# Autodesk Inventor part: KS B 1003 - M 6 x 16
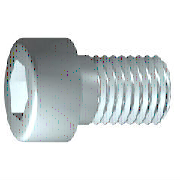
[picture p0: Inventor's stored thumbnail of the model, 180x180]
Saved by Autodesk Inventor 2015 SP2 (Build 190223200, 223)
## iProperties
Created: 2009-02
Part Number: KS B 1003 - M 6 x 16
Material: Steel, Mild
Description: 6각머리 태핑 나사
Document SubType Name: Modeling
Standard: KS B 1003
Designer: KYOUNG IL JANG
Standards Organization: KS
Language: ko-KR
Size Designation: M 6 x 16
Categories: <MemberInstance><Categories><Category DisplayName="조임쇠" InternalName="e4da775c-781d-43d5-af7c-5136215cf5a6" Mnemonic="FSTN"><Category DisplayName="볼트" InternalN
Density: 1 g/cm^3
Appearance: Metal-Steel
Company: 한국ATC센터
IsCustomPart: 0
Author: KYOUNG IL JANG
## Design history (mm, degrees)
sketch "스케치1"
  geometry: L1 (-1.333, 0)-(16, 0); L2 (16, 0)-(16, 3); L3 (16, 3)-(2.5, 3); L4 (2.5, 3)-(1.886, 3); L5 (1.886, 3)-(0, 3); L6 (0, 3)-(0, 5); L7 (0, 5)-(-6, 5); L8 (-6, 5)-(-6, 2.887); L9 (-6, 2.887)-(-3, 2.887); L10 (-3, 2.887)-(-1.333, 0); L11 (-10.4, 0)-(20.4, 0) reference; L12 (0, -1)-(0, 6) reference; L13 (2.5, 3)-(0, 3)
  constraints: 22 end point, 6 parallel, 2 collinear, 2 perpendicular, 1 horizontal, 1 point on line
  dimensions: "d1" = 13.5 distance from line of L3.end L2 (= GEL); "d2" = 0.61355 distance of L4.end L3.end (computed from GAL); "d3" = 6 distance between parallel lines of L8 L6 (= KOH); "d4" = 3 distance of L8.end L9.end (= INTI); "d5" = 60 deg angle of L10 L1; "d6" = 6 diameter of L3 L1 (= GD); "d7" = 6 diameter of L5 L1 (= BDM); "d8" = 5.7735 diameter of L9 L1 (= 1.1547 x SW); "d9" = 10 diameter of L7 L1 (= KOD); "d26" = 16 distance between parallel lines of L12 L2 (= NLG)
revolve "본체" sketch "스케치1" stored, may be unused: angle "d10" = 90 deg
sketch "스케치2"
  geometry: L1 (0, -7)-(0, 7) reference; L2 (-7, 0)-(7, 0) reference; L3 (2.887, 0)-(1.443, -2.5); L4 (1.443, -2.5)-(-1.443, -2.5); L5 (-1.443, -2.5)-(-2.887, 0); L6 (-2.887, 0)-(-1.443, 2.5); L7 (-1.443, 2.5)-(1.443, 2.5); L8 (1.443, 2.5)-(2.887, 0); 2 further points
  constraints: 12 end point, 1 coincident, 1 horizontal alignment, 1 point on line, 12 other
extrude "슬롯" join sketch "스케치2" stored distance "d11" = 10; taper "d12" = 0 deg
workplane "Work Plane1"
fillet "Fillet2" dims "d30" = 0.1 (= R)
body "Solid1"
fillet "모깎기1" dims "d17" = 0.6 (= RR)
feature "스레드" dims "d13" = 13.5 (= GEL), "d14" = 0
chamfer "모따기1" distance "d15" = 0.61345 (= -0.5 x SPD + 0.5 x GD); stored, may be unused: second distance "d16" = 0.61345 (= GUL), angle "d27" = 45 deg
other parameters: "GD" = 6 (= NND) [user parameter; used in 2 equation terms], "NLG" = 16 [user parameter; used in 1 equation term], "GEL" = 13.5 [user parameter; used in 2 equation terms], "KOD" = 10 [user parameter; used in 1 equation term], "KOH" = 6 [user parameter; used in 1 equation term], "INTI" = 3 [user parameter; used in 1 equation term], "GAL" = 0.61345 (= 0.61345 x PTC) [user parameter; used in 1 equation term], "GUL" = 0.61345 (= 0.61345 x PTC) [user parameter; used in 1 equation term], "BDM" = 6 (= NND) [user parameter; used in 1 equation term], "SW" = 5 [user parameter; used in 2 equation terms], "RR" = 0.6 [user parameter; used in 1 equation term], "SPD" = 4.7731 (= NND - 1.2269 x PTC) [user parameter; used in 1 equation term], "d19" = 0, "d28" = 0, "d29" = 0, "R" = 0.1 [user parameter; used in 1 equation term], "PHH" = 0.25 [user parameter], "GD1" = 4.7731 (= THREADDIA - 1.2269 x PTC) [user parameter], "THREADDIA" = 6 [user parameter; used in 1 equation term], "FAWI" = 45 deg [user parameter], "PTC" = 1 [user parameter; used in 5 equation terms], "NND" = 6 [user parameter; used in 3 equation terms], "TOA" = 30 deg [user parameter], "E0" = 5.775 (= 1.155 x SW) [user parameter]
